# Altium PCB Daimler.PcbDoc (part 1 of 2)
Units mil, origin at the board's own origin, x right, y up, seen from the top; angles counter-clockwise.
Board outline 11850 x 8035 mil, 2 copper layers (Top Layer, Bottom Layer); 112 components, 172 nets, 625 pads, 65 vias.
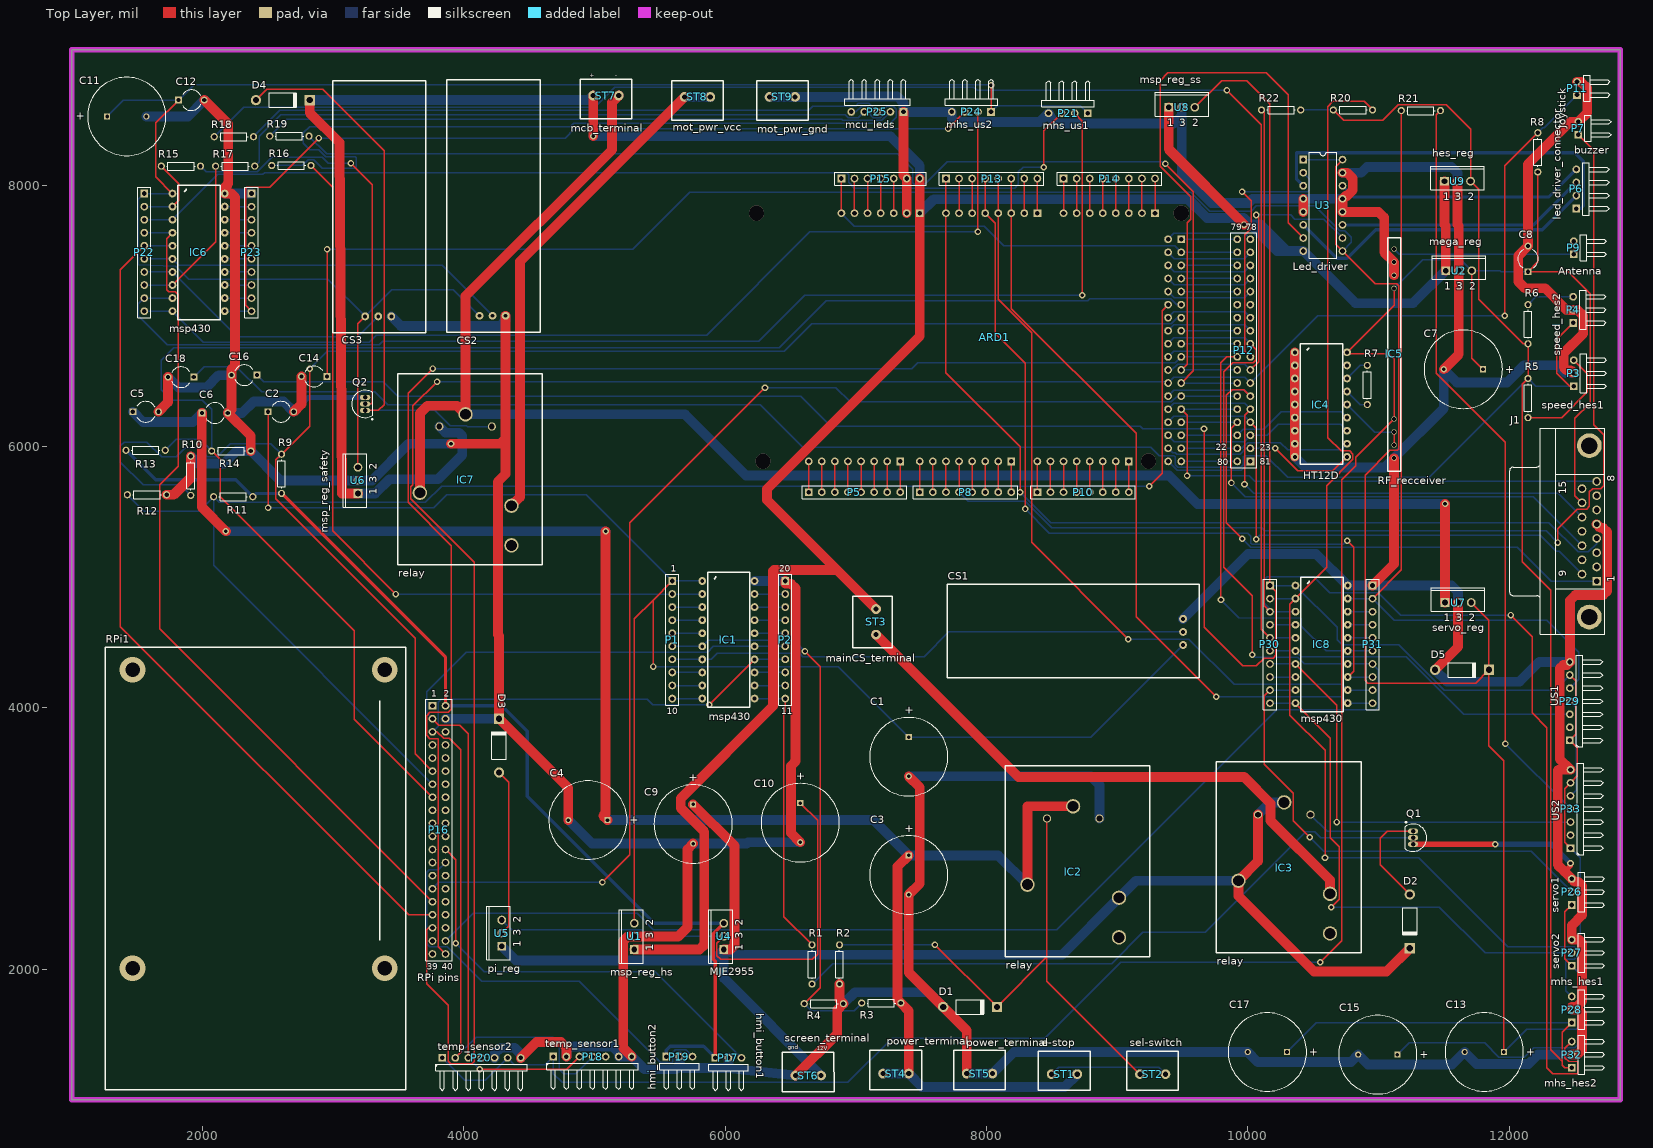
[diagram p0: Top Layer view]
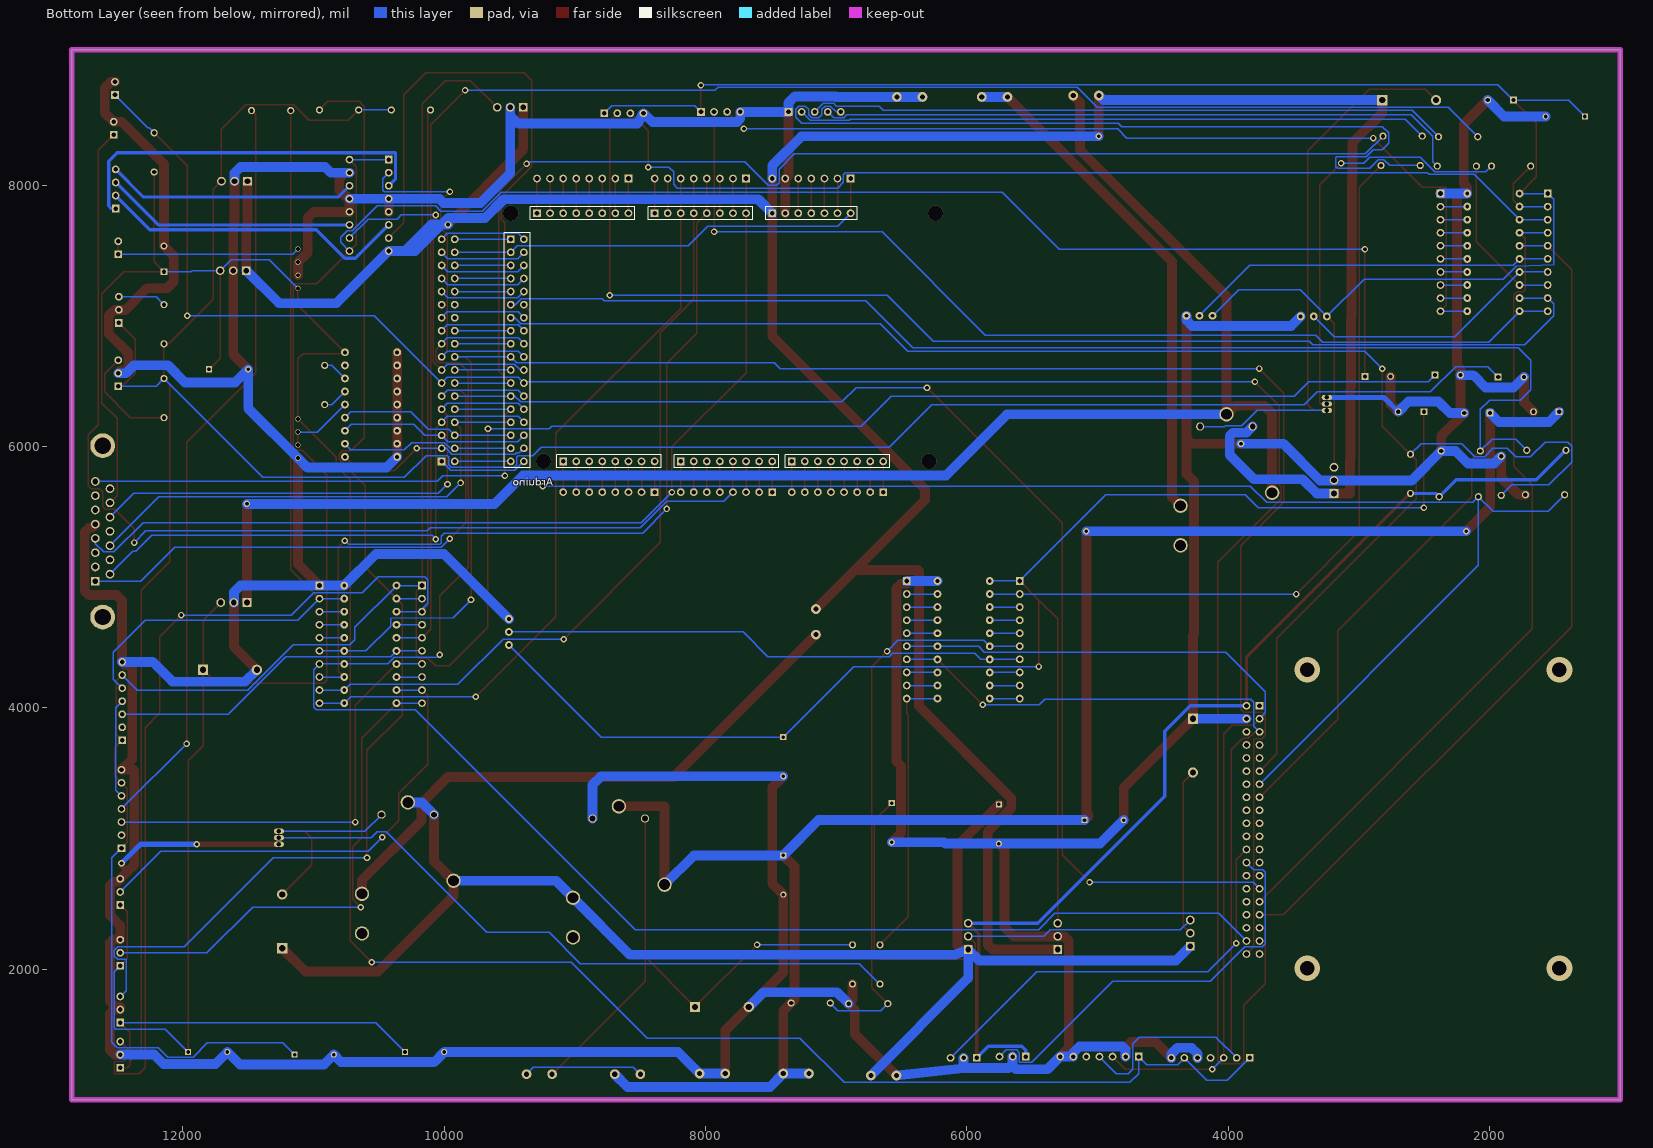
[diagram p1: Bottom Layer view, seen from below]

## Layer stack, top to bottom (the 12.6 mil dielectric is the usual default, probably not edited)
Top Solder: solder mask 0.4, Solder Resist, Dk 3.5
Top Layer: signal copper 1.4
Dielectric 1: dielectric 12.6, FR-4, Dk 4.8
Bottom Layer: signal copper 1.4
Bottom Solder: solder mask 0.4, Solder Resist, Dk 3.5

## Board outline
1000,1000 1000,9035 12850,9035 12850,1000

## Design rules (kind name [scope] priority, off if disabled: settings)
Clearance [All] p1: gap=10
PolygonConnect [All] p1: connectstyle=Relief reliefconductorwidth=10 reliefentries=4 polygonreliefangle="90 Angle" airgapwidth=10
RoutingVias [All] p1: holewidth=28 width=50 viastyle="Through Hole" minholewidth=28 minwidth=50 maxholewidth=28 maxwidth=50
SolderMaskExpansion [All] p1: expansion=4
Width "Schematic Width Constraint_11" [InNet('12V_MOTOR_DRIVER')] p1: maxlimit=80 minlimit=70 preferedwidth=75
Width "Schematic Width Constraint_10" [InNet('12V_MCB')] p2: maxlimit=80 minlimit=70 preferedwidth=75
Width "Schematic Width Constraint_9" [InNet('GND')] p3: maxlimit=80 minlimit=40 preferedwidth=75
Width "Schematic Width Constraint_8" [InNet('12V_TO_MAINCS')] p4: maxlimit=80 minlimit=70 preferedwidth=75
Width "Schematic Width Constraint_7" [InNet('12V_RPI')] p5: maxlimit=80 minlimit=70 preferedwidth=75
Width "Schematic Width Constraint_6" [InNet('12V_MAIN')] p6: maxlimit=80 minlimit=70 preferedwidth=75
Width "Schematic Width Constraint_3" [InNet('LED_SINK')] p7: maxlimit=30 minlimit=20 preferedwidth=25
Width "Schematic Width Constraint_2" [InNet('GREEN_OP')] p8: maxlimit=30 minlimit=20 preferedwidth=25
Width "Schematic Width Constraint_1" [InNet('BLUE_OP')] p9: maxlimit=30 minlimit=20 preferedwidth=25
Width "Schematic Width Constraint_5" [InNet('VCC_PI')] p10: maxlimit=30 minlimit=20 preferedwidth=25
Width "Schematic Width Constraint_4" [InNet('RED_OP')] p11: maxlimit=30 minlimit=20 preferedwidth=25
Width "Schematic Width Constraint" [InNet('12V')] p12: maxlimit=80 minlimit=70 preferedwidth=75
Width [All] p13: maxlimit=10 minlimit=10 preferedwidth=10
30 further rules are at their usual default settings.

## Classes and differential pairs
component class HardStop: C1 C2 C3 C4 C5 C6 CS1 D1 D2 IC1 IC2 IC3 P1 P2 Q1 R1 R2 R3 R4 ST1 ST2 ST3 ST4 ST5 U1
component class Navigation: ARD1 C7 C8 IC4 IC5 J1 P3 P4 P5 P6 P7 P8 P9 P10 P11 P12 P13 P14 P15 R5 R6 R7 R8 U2 U3
component class RPi: C9 C10 D3 P16 P17 P18 P19 P20 R9 R10 R11 R12 R13 R14 RPi1 ST6 U4 U5
component class Safety: C11 C12 CS2 CS3 D4 IC6 IC7 P21 P22 P23 P24 P25 Q2 R15 R16 R17 R18 R19 ST7 ST8 ST9 U6
component class SoftStop: C13 C14 C15 C16 C17 C18 D5 IC8 P26 P27 P28 P29 P30 P31 P32 P33 R20 R21 R22 U7 U8 U9

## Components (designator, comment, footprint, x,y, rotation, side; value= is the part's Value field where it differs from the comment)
ARD1 "Arduino" Arduino 7790,6785 r0 top
C1 "Cap Pol1" RB7.6-15 7405,3625 r90 top
C2 "Cap2" CAPR5-4X5 2600,6265 r0 top
C3 "Cap Pol1" RB7.6-15 7405,2720 r90 top
C4 "Cap Pol1" RB7.6-15 4950,3140 r0 top
C5 "Cap2" CAPR5-4X5 1565,6265 r0 top
C6 "Cap2" CAPR5-4X5 2095,6255 r0 top
C7 "Cap" RB7.6-15 11650,6590 r0 top
C8 "Cap2" CAPR5-4X5 12145,7435 r90 top
C9 "Cap" RB7.6-15 5755,3110 r90 top
C10 "Cap" RB7.6-15 6575,3120 r90 top
C11 "Cap" RB7.6-15 1420,8525 r180 top
C12 "Cap2" CAPR5-4X5 1915,8650 r0 top
C13 "Cap" RB7.6-15 11810,1365 r0 top
C14 "Cap2" CAPR5-4X5 2855,6535 r180 top
C15 "Cap" RB7.6-15 10995,1345 r0 top
C16 "Cap2" CAPR5-4X5 2320,6545 r180 top
C17 "Cap Pol1" RB7.6-15 10150,1365 r0 top
C18 "Cap2" CAPR5-4X5 1835,6530 r180 top
CS1 "CS3" ACS712 9405,4565 r180 top
CS2 "CS1" ACS712 4205,7100 r90 top
CS3 "CS2" ACS712 3330,7095 r90 top
D1 "flyback relay" DO-41 7875,1710 r0 top
D2 "flyback relay" DO-41 11240,2365 r270 top
D3 "cur_amp" DO-41 4270,3710 r90 top
D4 "flyback relay" DO-41 2615,8650 r0 top
D5 "Diode 1N4001" DO-41 11640,4290 r0 top
IC1 "msp430" msp430 6035,4575 r270 top
IC2 "relay" "relay JQX 15F" 8665,2825 r90 top
IC3 "relay" "relay JQX 15F" 10280,2855 r90 top
IC4 "HT12D" HT12D 10575,6325 r270 top
IC5 "RF_recceiver" RF_434_receiver 11120,6705 r90 top
IC6 "msp430" msp430 1980,7540 r270 top
IC7 "relay" "relay JQX 15F" 4015,5825 r90 top
IC8 "msp430" msp430 10575,4540 r270 top
J1 "D Connector 15" DSUB1.385-2H15 12240,5350 r90 top
P1 "hs_connector1" HDR1X10 5595,4970 r270 top
P2 "hs_connector2" HDR1X10 6460,4970 r270 top
P3 "speed_hes1" HDR1X3H 12495,6460 r90 top
P4 "speed_hes2" HDR1X3H 12490,6945 r90 top
P5 "Header 8" HDR1X8 6640,5650 r0 top
P6 "led_driver_connector" HDR1X4H 12515,7820 r90 top
P7 "buzzer" HDR1X2H 12530,8385 r90 top
P8 "Header 8" HDR1X8 7490,5650 r0 top
P9 "Antenna" HDR1X2H 12495,7470 r90 top
P10 "Header 8" HDR1X8 8390,5650 r0 top
P11 "Joystick" HDR1X2H 12520,8690 r90 top
P12 "Header 18X2" HDR2X18 10020,5885 r90 top
P13 "Header 8" HDR1X8 7690,8050 r0 top
P14 "Header 8" HDR1X8 8590,8050 r0 top
P15 "Header 7" HDR1X7 6890,8050 r0 top
P16 "RPi pins" HDR2X20 3760,4015 r270 top
P17 "hmi_button1" HDR1X3H 5925,1320 r0 top
P18 "temp_sensor1" HDR1X7H 4685,1330 r0 top
P19 "hmi_button2" HDR1X3H 5550,1330 r0 top
P20 "temp_sensor2" HDR1X7H 3835,1320 r0 top
P21 "mhs_us1" HDR1X4H 8775,8550 r180 top
P22 "safety_connector1" HDR1X10 1555,7935 r270 top
P23 "safety_connector2" HDR1X10 2375,7935 r270 top
P24 "mhs_us2" HDR1X4H 8035,8560 r180 top
P25 "mcu_leds" HDR1X5H 7365,8560 r180 top
P26 "servo1" HDR1X3H 12480,2490 r90 top
P27 "servo2" HDR1X3H 12480,2025 r90 top
P28 "mhs_hes1" HDR1X3H 12480,1590 r90 top
P29 "US1" HDR1X7H 12465,3750 r90 top
P30 "ss_connector1" HDR1X10 10170,4935 r270 top
P31 "ss_connector2" HDR1X10 10955,4935 r270 top
P32 "mhs_hes2" HDR1X3H 12480,1245 r90 top
P33 "US2" HDR1X7H 12470,2925 r90 top
Q1 "NPN" TO-226-AA 11265,3005 r180 top
Q2 "NPN" TO-226-AA 3245,6325 r0 top
R1 "Res1" AXIAL-0.3 6665,2035 r90 top
R2 "Res1" AXIAL-0.3 6875,2035 r90 top
R3 "Res1" AXIAL-0.3 7195,1740 r180 top
R4 "Res1" AXIAL-0.3 6755,1735 r0 top
R5 "Res1" AXIAL-0.3 12145,6370 r90 top
R6 "Res1" AXIAL-0.3 12145,6935 r270 top
R7 "Res1" AXIAL-0.3 10915,6470 r270 top
R8 "Res1" AXIAL-0.3 12220,8250 r90 top
R9 "Res1" AXIAL-0.3 2605,5790 r90 top
R10 "Res1" AXIAL-0.3 1910,5775 r90 top
R11 "Res1" AXIAL-0.3 2235,5615 r180 top
R12 "Res1" AXIAL-0.3 1575,5630 r180 top
R13 "Res1" AXIAL-0.3 1565,5970 r0 top
R14 "Res1" AXIAL-0.3 2220,5965 r180 top
R15 "Res1" AXIAL-0.3 1835,8145 r180 top
R16 "Res1" AXIAL-0.3 2680,8150 r180 top
R17 "Res1" AXIAL-0.3 2250,8145 r0 top
R18 "Res1" AXIAL-0.3 2240,8370 r0 top
R19 "Res1" AXIAL-0.3 2665,8375 r180 top
R20 "Res1" AXIAL-0.3 10805,8575 r0 top
R21 "Res1" AXIAL-0.3 11325,8570 r180 top
R22 "Res1" AXIAL-0.3 10255,8575 r180 top
RPi1 "raspberrypi" raspberrypi 1465,4290 r270 top
ST1 "e-stop" screw_terminal_5 8610,1195 r180 top
ST2 "sel-switch" screw_terminal_5 9285,1195 r180 top
ST3 "mainCS_terminal" screw_terminal_5 7155,4670 r270 top
ST4 "power_terminal" screw_terminal_5 7320,1200 r180 top
ST5 "power_terminal" screw_terminal_5 7960,1200 r180 top
ST6 "screen_terminal" screw_terminal_5 6650,1185 r180 top
ST7 "mcb_terminal" screw_terminal_5 5075,8685 r0 top
ST8 "mot_pwr_vcc" screw_terminal_5 5775,8675 r0 top
ST9 "mot_pwr_gnd" screw_terminal_5 6425,8675 r0 top
U1 "msp_reg_hs" TO220ABN 5305,2250 r90 top
U2 "mega_reg" TO220ABN 11615,7345 r0 top
U3 "Led_driver" DIP16 10575,7845 r270 top
U4 "MJE2955" TO220ABN 5990,2250 r90 top
U5 "pi_reg" TO220ABN 4290,2275 r90 top
U6 "msp_reg_safety" TO220ABN 3190,5740 r90 top
U7 "servo_reg" TO220ABN 11610,4805 r0 top
U8 "msp_reg_ss" TO220ABN 9495,8595 r0 top
U9 "hes_reg" TO220ABN 11605,8030 r0 top

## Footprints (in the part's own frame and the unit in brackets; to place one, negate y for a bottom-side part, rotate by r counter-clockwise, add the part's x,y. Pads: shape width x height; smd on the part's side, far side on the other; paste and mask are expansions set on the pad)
ACS712 [mil]
  round 60 hole 30: 1(-100,85) 2(-100,-15) 3(-100,-115)
  silkscreen extent -225,-380 1705,335, body extent -230,-380 1705,335, height 787
Arduino [mm] "Arduino Mega 2560"
  rect 1.5x1.5 hole 0.9: 0(10.16,-22.86) 8(-11.43,-22.86) 21(33.02,-22.86) 59(-7.62,25.4) 67(15.24,25.4) 75(38.1,25.4) 79(43.18,20.32)
  round 1.5 hole 0.9: 1(7.62,-22.86) 2(5.08,-22.86) 3(2.54,-22.86) 4(0,-22.86) 5(-2.54,-22.86) 6(-5.08,-22.86) 7(-7.62,-22.86) 9(-13.97,-22.86) 10(-16.51,-22.86) 11(-19.05,-22.86) 12(-21.59,-22.86) 13(-24.13,-22.86) 14(15.24,-22.86) 15(17.78,-22.86) 16(20.32,-22.86) 17(22.86,-22.86) 18(25.4,-22.86) 19(27.94,-22.86) 20(30.48,-22.86) 22(40.64,-20.32) 23(43.18,-20.32) 24(40.64,-17.78) 25(43.18,-17.78) 26(40.64,-15.24) 27(43.18,-15.24) 28(40.64,-12.7) 29(43.18,-12.7) 30(40.64,-10.16) 31(43.18,-10.16) 32(40.64,-7.62) 33(43.18,-7.62) 34(40.64,-5.08) 35(43.18,-5.08) 36(40.64,-2.54) 37(43.18,-2.54) 38(40.64,0) 39(43.18,0) 40(40.64,2.54) 41(43.18,2.54) 42(40.64,5.08) 43(43.18,5.08) 44(40.64,7.62) 45(43.18,7.62) 46(40.64,10.16) 47(43.18,10.16) 48(40.64,12.7) 49(43.18,12.7) 50(40.64,15.24) 51(43.18,15.24) 52(40.64,17.78) 53(-22.86,25.4) 53(43.18,17.78) 54(-20.32,25.4) 55(-17.78,25.4) 56(-15.24,25.4) 57(-12.7,25.4) 58(-10.16,25.4) 60(-2.54,25.4) 61(0,25.4) 62(2.54,25.4) 63(5.08,25.4) 64(7.62,25.4) 65(10.16,25.4) 66(12.7,25.4) 68(20.32,25.4) 69(22.86,25.4) 70(25.4,25.4) 71(27.94,25.4) 72(30.48,25.4) 73(33.02,25.4) 74(35.56,25.4) 76(-26.67,-22.86) 77(-29.21,-22.86) 78(40.64,20.32) 80(43.18,-22.86) 81(40.64,-22.86)
AXIAL-0.3 [mm] "Axial Device, Thru-Hole; 2 Leads; 0.3 in Pin Spacing"
  round 1.4 hole 0.85: 1(-3.81,0) 2(3.81,0)
  silkscreen extent -2.77,-0.76 2.77,0.76
CAPR5-4X5 [mm] "Capacitor; 2 Leads"
  rect 1.35x1.35 hole 0.8: 1(-2.5,0)
  round 1.35 hole 0.8: 2(2.5,0)
  silkscreen extent -1.69,-2 1.82,2
DIP16 [mm] "DIP; 16 Leads; Row Spacing 7.62 mm; Pitch 2.54 mm"
  rect 1.5x1.5 hole 0.9: 1(-8.89,-3.81)
  round 1.5 hole 0.9: 2(-6.35,-3.81) 3(-3.81,-3.81) 4(-1.27,-3.81) 5(1.27,-3.81) 6(3.81,-3.81) 7(6.35,-3.81) 8(8.89,-3.81) 9(8.89,3.81) 10(6.35,3.81) 11(3.81,3.81) 12(1.27,3.81) 13(-1.27,3.81) 14(-3.81,3.81) 15(-6.35,3.81) 16(-8.89,3.81)
  silkscreen extent -10.3,-2.65 10.3,2.65
DO-41 [mm] "Diode, Axial; Body 5.2 x 2.7 mm (LxDia. max), Lead Dia. 0.86 mm (max)"
  round 2 hole 1.2: 1(-5.23,0)
  rect 2x2 hole 1.2: 2(5.23,0)
  silkscreen extent -2.65,-1.4 2.75,1.4
DSUB1.385-2H15 [mm] "Connector; D Subminiature; 15 Position; Right Angle; Pitch 1.385 mm"
  rect 1.69x1.69 hole 1.09: 1(-9.695,-10.92)
  round 1.69 hole 1.09: 2(-6.925,-10.92) 3(-4.155,-10.92) 4(-1.385,-10.92) 5(1.385,-10.92) 6(4.155,-10.92) 7(6.925,-10.92) 8(9.695,-10.92) 9(-8.31,-8.08) 10(-5.54,-8.08) 11(-2.77,-8.08) 12(0,-8.08) 13(2.77,-8.08) 14(5.54,-8.08) 15(8.31,-8.08)
  round 4.8 hole 3.18: 16(-16.66,-9.5) 17(16.66,-9.5)
  silkscreen extent -20,-12.5 20,6
HDR1X2H [mm] "Connector; Header; 2 Position; Right Angle"
  rect 1.5x1.5 hole 0.9: 1(0,0)
  round 1.5 hole 0.9: 2(2.54,0)
  silkscreen extent -1.27,-6.35 3.81,-1.27
HDR1X3H [mm] "Connector; Header; 3 Position; Right Angle"
  rect 1.5x1.5 hole 0.9: 1(0,0)
  round 1.5 hole 0.9: 2(2.54,0) 3(5.08,0)
  silkscreen extent -1.27,-6.35 6.35,-1.27
HDR1X4H [mm] "Connector; Header; 4 Position; Right Angle"
  rect 1.5x1.5 hole 0.9: 1(0,0)
  round 1.5 hole 0.9: 2(2.54,0) 3(5.08,0) 4(7.62,0)
  silkscreen extent -1.27,-6.35 8.89,-1.27
HDR1X5H [mm] "Connector; Header; 5 Position; Right Angle"
  rect 1.5x1.5 hole 0.9: 1(0,0)
  round 1.5 hole 0.9: 2(2.54,0) 3(5.08,0) 4(7.62,0) 5(10.16,0)
  silkscreen extent -1.27,-6.35 11.43,-1.27
HDR1X7 [mm] "Connector; Header; 7 Position"
  rect 1.5x1.5 hole 0.9: 1(0,0)
  round 1.5 hole 0.9: 2(2.54,0) 3(5.08,0) 4(7.62,0) 5(10.16,0) 6(12.7,0) 7(15.24,0)
  silkscreen extent -1.27,-1.27 16.51,1.27
HDR1X7H [mm] "Connector; Header; 7 Position; Right Angle"
  rect 1.5x1.5 hole 0.9: 1(0,0)
  round 1.5 hole 0.9: 2(2.54,0) 3(5.08,0) 4(7.62,0) 5(10.16,0) 6(12.7,0) 7(15.24,0)
  silkscreen extent -1.27,-6.35 16.51,-1.27
HDR1X8 [mm] "Connector; Header; 8 Position"
  rect 1.5x1.5 hole 0.9: 1(0,0)
  round 1.5 hole 0.9: 2(2.54,0) 3(5.08,0) 4(7.62,0) 5(10.16,0) 6(12.7,0) 7(15.24,0) 8(17.78,0)
  silkscreen extent -1.27,-1.27 19.05,1.27
HDR1X10 [mm] "Connector; Header; 10 Position"
  rect 1.5x1.5 hole 0.9: 1(0,0)
  round 1.5 hole 0.9: 2(2.54,0) 3(5.08,0) 4(7.62,0) 5(10.16,0) 6(12.7,0) 7(15.24,0) 8(17.78,0) 9(20.32,0) 10(22.86,0)
  silkscreen extent -1.27,-1.27 24.13,1.27
HDR2X18 [mm] "Connector; Header; 18x2 Position"
  rect 1.5x1.5 hole 0.9: 1(0,0)
  round 1.5 hole 0.9: 2(0,2.54) 3(2.54,0) 4(2.54,2.54) 5(5.08,0) 6(5.08,2.54) 7(7.62,0) 8(7.62,2.54) 9(10.16,0) 10(10.16,2.54) 11(12.7,0) 12(12.7,2.54) 13(15.24,0) 14(15.24,2.54) 15(17.78,0) 16(17.78,2.54) 17(20.32,0) 18(20.32,2.54) 19(22.86,0) 20(22.86,2.54) 21(25.4,0) 22(25.4,2.54) 23(27.94,0) 24(27.94,2.54) 25(30.48,0) 26(30.48,2.54) 27(33.02,0) 28(33.02,2.54) 29(35.56,0) 30(35.56,2.54) 31(38.1,0) 32(38.1,2.54) 33(40.64,0) 34(40.64,2.54) 35(43.18,0) 36(43.18,2.54)
  silkscreen extent -1.27,-1.27 44.45,3.81
HDR2X20 [mm] "Connector; Header; 20x2 Position"
  rect 1.5x1.5 hole 0.9: 1(0,0)
  round 1.5 hole 0.9: 2(0,2.54) 3(2.54,0) 4(2.54,2.54) 5(5.08,0) 6(5.08,2.54) 7(7.62,0) 8(7.62,2.54) 9(10.16,0) 10(10.16,2.54) 11(12.7,0) 12(12.7,2.54) 13(15.24,0) 14(15.24,2.54) 15(17.78,0) 16(17.78,2.54) 17(20.32,0) 18(20.32,2.54) 19(22.86,0) 20(22.86,2.54) 21(25.4,0) 22(25.4,2.54) 23(27.94,0) 24(27.94,2.54) 25(30.48,0) 26(30.48,2.54) 27(33.02,0) 28(33.02,2.54) 29(35.56,0) 30(35.56,2.54) 31(38.1,0) 32(38.1,2.54) 33(40.64,0) 34(40.64,2.54) 35(43.18,0) 36(43.18,2.54) 37(45.72,0) 38(45.72,2.54) 39(48.26,0) 40(48.26,2.54)
  silkscreen extent -1.27,-1.27 49.53,3.81
HT12D [mil]
  round 60 hole 30: 1(-395,-215) 2(-295,-215) 3(-195,-215) 4(-95,-215) 5(5,-215) 6(105,-215) 7(205,-215) 8(305,-215) 9(405,-215) 10(405,185) 11(305,185) 12(205,185) 13(105,185) 14(5,185) 15(-95,185) 16(-195,185) 17(-295,185) 18(-395,185)
  silkscreen extent -460,-175 460,150, body extent -460,-175 455,150, height 325
msp430 [mil]
  round 60 hole 30: 1(-395,-210) 2(-295,-210) 3(-195,-210) 4(-95,-210) 5(5,-210) 6(105,-210) 7(205,-210) 8(305,-210) 9(405,-210) 10(505,-210) 11(505,190) 12(405,190) 13(305,190) 14(205,190) 15(105,190) 16(5,190) 17(-95,190) 18(-195,190) 19(-295,190) 20(-395,190)
  silkscreen extent -460,-170 570,155, body extent -460,-170 565,155, height 325
raspberrypi [mil]
  silkscreen extent -173,-209 3213,2091, body extent 2766,53 3301,1781, height 591
RB7.6-15 [mm] "Polarized Capacitor (Radial); 2 Leads"
  rect 1.2x1.2 hole 0.7: 1(3.81,0)
  round 1.2 hole 0.7: 2(-3.81,0)
  silkscreen extent -7.62,-7.62 7.62,7.62
"relay JQX 15F" [mm]
  round 2.8 hole 2.1: 1(-14.8,-8.875) 2(-7.1,-8.875) 3(-4.55,8.925) 6(10.675,0.05)
  round 1.6 hole 1.1: 4(8.3,5.125) 5(8.3,-5.075)
  silkscreen extent -18.52,-14.9 18.55,13.23, body extent -18.52,-14.88 18.5,13.15, height 20.4
RF_434_receiver [mil]
  round 40 hole 30: 1(-795,0) 2(-695,0) 3(-595,0) 4(-495,0) 5(505,0) 6(605,0) 7(705,0) 8(805,0)
  silkscreen extent -895,-50 890,50, body extent -895,-45 890,50, height 413
screw_terminal_5 [mm]
  round 1.9 hole 1: 1(-2.159,0) 2(2.819,0)
  silkscreen extent -4.67,-4.5 5.38,3.12, body extent -4.52,-4.34 5.23,3, height 10
TO220ABN [mm] "TO, Thru-Hole, Vertical, Heatsink Mounted; 3 In-Line Leads; Pitch 2.54 mm; Pin sequence 1, 3, 2"
  rect 1.7x1.7 hole 1.1: 1(-2.54,0)
  round 1.7 hole 1.1: 2(2.54,0) 3(0,0)
  silkscreen extent -5.2,-1.7 5.2,2.9
TO-226-AA [mm] "TO, Flat Index; 3 In-Line, Axial Leads; Body Dia. 4.8mm; Leads 0.55 x 0.51 mm (max)"
  oval 2x1 hole 0.9: 1(0,-1.27) 2(0,0) 3(0,1.27)
  silkscreen extent -2.65,-3.13 1.52,2.65, body extent -2.66,-2.66 1.52,2.66, height 5.33

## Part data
C1 C3 C4 C17: "Polarized Capacitor (Radial)"
C2 C5 C6 C8 C12 C14 C16 C18: "Capacitor"
C7 C9 C10 C11 C13 C15: library part "Cap Pol1", "Polarized Capacitor (Radial)"
CS1 CS2 CS3: library part ACS712
D1 D2 D3 D4: library part "Diode 1N4001", "1 Amp General Purpose Rectifier"
D5: "1 Amp General Purpose Rectifier"
IC2 IC3 IC7: library part "relay JQX-15F"
IC5: library part RF434_receiver
J1: "Receptacle Assembly, 15 Position, Right Angle"
P1 P2 P22 P23 P30 P31: library part "Header 10", "Header, 10-Pin"
P3 P4 P17 P19 P26 P27 P28 P32: library part "Header 3H", "Header, 3-Pin, Right Angle"
P5 P8 P10 P13 P14: "Header, 8-Pin"
P6 P21 P24: library part "Header 4H", "Header, 4-Pin, Right Angle"
P7 P9 P11: library part "Header 2H", "Header, 2-Pin, Right Angle"
P12: "Header, 18-Pin, Dual row"
P15: "Header, 7-Pin"
P16: library part "Header 20X2", "Header, 20-Pin, Dual row"
P18 P20 P29 P33: library part "Header 7H", "Header, 7-Pin, Right Angle"
P25: library part "Header 5H", "Header, 5-Pin, Right Angle"
Q1 Q2: "NPN Bipolar Transistor"
R1 R2 R3 R4 R5 R6 R7 R8 R9 R10 R11 R12 R13 R14 R15 R16 R17 R18 R19 R20 R21 R22: "Resistor"
ST1 ST2 ST3 ST4 ST5 ST6 ST7 ST8 ST9: library part screw_terminal
U1 U2 U4 U5 U6 U7 U8 U9: library part L7805CV, "Positive Voltage Regulator"
U3: library part L293D, "Push-Pull Four Channel Driver With Diode"

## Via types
v1: diameter 50, hole 28, Top Layer to Bottom Layer, 57 vias
v2: diameter 196.85, hole 110.24, Top Layer to Bottom Layer, 4 vias
v3: diameter 118.11, hole 118.11, Top Layer to Bottom Layer, 4 vias

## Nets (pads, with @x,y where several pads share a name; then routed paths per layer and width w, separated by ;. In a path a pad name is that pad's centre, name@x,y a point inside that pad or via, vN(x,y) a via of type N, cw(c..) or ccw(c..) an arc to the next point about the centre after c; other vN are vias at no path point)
12V: ARD1.59 D4.2 IC7.4 P15.7 ST3.1 ST7.1 U1.1 U2.1 U3.8 U6.1 U8.1 U9.1 | length 24818.3
  Top Layer w75: D4.2@2820.91,8650 2820.91,8553.09 3047.5,8326.5 3068,5640 U6.1@3190,5640 ; v1(4990,8373) ST7.1@4990,8685 ; U1.1@5305,2150 5804,2150 5840,2186 5840,3051 5660,3231 5660,3305 6367,4012 6367,5047 6375,5055 6855,5055 ; ST3.1@7155,4755 6855,5055 ; P15.7@7490,8050 ARD1.59@7490,7785 7490,6845 6320,5675 6320,5590 6855,5055 ; U8.1@9395,8595 9395,8274 v1(9971,7698) ; U9.1@11505,8030 11505,7698 11515,7688 U2.1@11515,7345
  Bottom Layer w75: D4.2@2820.91,8650 4955,8650 ST7.1@4990,8685 ; U6.1@3190,5640 3321.51,5640 3430,5748.49 3803.49,5748.49 3988,5933 3988,6080 3963,6105 3860,6105 IC7.4@3813.23,6151.77 ; v1(4990,8373) 7265,8373 7490,8148 P15.7@7490,8050 ; ARD1.59@7490,7785 7596.56,7891.56 9544.44,7891.56 9687.73,7748.27 9969.73,7748.27 10020,7698 ; v1(9971,7698) 10020,7698 ; U2.1@11515,7345 11266,7096 10824,7096 U3.8@10425,7495 10300,7495 ; 10020,7698 10097,7698 10300,7495 ; 10020,7698 10223,7495 10300,7495
12V_MAIN: C3.1 C4.1 C5.1 C6.1 IC2.3 IC2.6 R3.1 ST1.1 ST4.1 ST4.2 | length 14386.9
  Top Layer w75: C6.1@1996.57,6255 1996.57,6198.85 1994,6196.28 1994,5948 1995,5947 1995,5534 v1(2179,5350) ; v1(5085,5350) 5085,3191 5067,3173 C4.1@5100,3140 ; ST4.1@7405,1200 7405,1680 R3.1@7345,1740 7320,1765 7320,2785 C3.1@7405,2870 ; IC2.3@8313.62,2645.87 8313.62,3245 8313.9,3245.28 IC2.6@8663.03,3245.28
  Bottom Layer w75: C5.1@1466.57,6265 1545.57,6186 1927.57,6186 C6.1@1996.57,6255 ; v1(2179,5350) v1(5085,5350) ; C4.1@5100,3140 7135,3140 C3.1@7405,2870 8089.49,2870 IC2.3@8313.62,2645.87 ; ST4.2@7209,1200 ST4.1@7405,1200 7507,1098 8598,1098 ST1.1@8695,1195
12V_MCB: IC7.3 IC7.6 ST7.2 U7.1 | length 12469.2
  Top Layer w75: IC7.3@3663.62,5645.87 3663.62,6253.93 3720,6310.31 3948,6310.31 IC7.6@4013.03,6245.28 4013.03,7150.03 5133,8270 5133,8632 ST7.2@5186,8685 ; U7.1@11510,4805 v1(11510,5560)
  Bottom Layer w75: IC7.6@4013.03,6245.28 5691.72,6245.28 6159,5778 9397,5778 9615,5560 v1(11510,5560)
12V_MOTOR_DRIVER: IC7.2 ST8.1 ST8.2 | length 3874.6
  Top Layer w75: IC7.2@4364.41,5545.47 4430,5611.06 4430,7415 ST8.1@5690,8675
  Bottom Layer w75: ST8.1@5690,8675 ST8.2@5886,8675
12V_RPI: C9.1 D2.2 IC2.2 IC3.3 IC3.4 IC3.6 ST6.1 U4.1 U5.1 | length 11089.1
  Top Layer w75: C9.1@5755,3260 6071,2944 6071,2180 6041,2150 U4.1@5990,2150 ; IC3.4@10078.23,3181.77 10078.23,2825.47 IC3.3@9928.62,2675.87 9928.62,2558.38 10507,1980 11060.91,1980 D2.2@11240,2159.09
  Bottom Layer w75: U5.1@4290,2175 4400,2065 5905,2065 U4.1@5990,2150 ; ST6.1@6735,1185 5990,1930 U4.1@5990,2150 ; IC3.3@9928.62,2675.87 9144.8,2675.87 IC2.2@9014.41,2545.47 8577.94,2109 6091,2109 U4.1@5990,2150 ; IC3.4@10078.23,3181.77 10171.73,3275.28 IC3.6@10278.03,3275.28
12V_TO_MAINCS: IC3.2 ST3.2 | length 4434.9
  Top Layer w75: ST3.2@7155,4559 8245,3469 9973,3469 10175,3267 10175,3135 10629.41,2680.59 IC3.2@10629.41,2575.47
BATTERY_LVL: IC1.6 P1.6 R3.2 R4.1 | length 4351
  Top Layer w10: R4.1@6605,1735 6728,1858 6728,4315 v1(6611,4432)
  Bottom Layer w10: P1.6@5595,4470 IC1.6@5825,4470 5870,4515 6528,4515 v1(6611,4432) ; R4.1@6605,1735 6657.5,1682.5 6987.5,1682.5 R3.2@7045,1740
BLUE: ARD1.35 P12.16 U3.7 | length 4990.3
  Top Layer w10: ARD1.35@9490,6585 9535,6630 9535,7711 9564.06,7740.06 9564.06,7908.94 9330,8143 9330,8800 9389,8859 10142,8859 10309,8692 10309,7711 U3.7@10425,7595
  Bottom Layer w10: ARD1.35@9490,6585 P12.16@9920,6585
BLUE_OP: P6.2 U3.6 | length 2394.4
  Bottom Layer w25: U3.6@10425,7695 10680,7440 10760,7440 10978,7658 12253,7658 P6.2@12515,7920
BUZZER_OP: ARD1.4 P7.1 P8.4 | length 8402.5
  Top Layer w10: P8.4@7790,5650 ARD1.4@7790,5885 ; v1(12372,5264) 12372,5371 12520,5519 12593,5519 12614,5540 12614,5651 12640,5677 12701,5677 12724,5700 12724,6088 12648,6164 12648,8267 P7.1@12530,8385
  Bottom Layer w10: P8.4@7790,5650 7859,5581 8296,5581 8501,5376 10106,5376 10129,5353 12283,5353 v1(12372,5264)
CS_IN1: CS2.2 IC6.6 P22.6 | length 2845.2
  Bottom Layer w10: P22.6@1555,7435 IC6.6@1770,7435 1820,7385 3835,7385 CS2.2@4220,7000
CS_IN2: CS3.2 IC6.7 P22.7 | length 2059.2
  Bottom Layer w10: P22.7@1555,7335 IC6.7@1770,7335 2265,6840 3190,6840 CS3.2@3345,6995
CS_IN3: CS1.2 IC1.7 P1.7 | length 4016.8
  Bottom Layer w10: P1.7@5595,4370 IC1.7@5825,4370 5893,4370 5938,4415 6570.5,4415 6594.42,4391.08 7522.08,4391.08 7711,4580 CS1.2@9505,4580
D0: ARD1.22 IC4.10 P12.3 | length 1523.7
  Top Layer w10: v1(10210,5985) 10383,5812 10652,5812 IC4.10@10760,5920
  Bottom Layer w10: ARD1.22@9390,5985 9425.47,5949.53 9445,5949.53 9454.53,5940 9940.47,5940 9985.47,5985 P12.3@10020,5985 v1(10210,5985)
D1: ARD1.23 IC4.11 P12.4 | length 1330.5
  Bottom Layer w10: ARD1.23@9490,5985 P12.4@9920,5985 9955.47,5985 10000,6029.53 10250,6029.53 10305.53,5974 10714,5974 IC4.11@10760,6020
D2: ARD1.24 IC4.12 P12.5 | length 1464.9
  Bottom Layer w10: ARD1.24@9390,6085 9438,6037 9972,6037 P12.5@10020,6085 10148,6085 10232,6169 10711,6169 IC4.12@10760,6120
D3: ARD1.25 IC4.13 P12.6 | length 1363.2
  Bottom Layer w10: ARD1.25@9490,6085 P12.6@9920,6085 9965,6130 10121,6130 10256,6265 10715,6265 IC4.13@10760,6220
FORK_LEFT: ARD1.30 J1.1 P12.11 | length 4886
  Top Layer w10: v1(9957,5294) 9835,5416 9835,6390 9880,6435 9970,6435 P12.11@10020,6385
  Bottom Layer w10: ARD1.30@9390,6385 9435,6430 9975,6430 P12.11@10020,6385 ; v1(9957,5294) 10021,5230 12062,5230 12323.69,4968.31 J1.1@12669.92,4968.31
FORK_RIGHT: ARD1.29 J1.8 P12.10 | length 4110.9
  Top Layer w10: ARD1.29@9490,6285 9535,6240 v1(9535,5776)
  Bottom Layer w10: ARD1.29@9490,6285 P12.10@9920,6285 ; v1(9535,5776) 10011,5776 10055,5732 12607,5732 12607.31,5731.69 J1.8@12669.92,5731.69
FROM_MSP: IC6.5 P16.33 P22.5 | length 6507.1
  Top Layer w10: P22.5@1555,7535 1372,7352 1372,4620 3577,2415 P16.33@3760,2415
  Bottom Layer w10: P22.5@1555,7535 IC6.5@1770,7535
GND: ARD1.58 C1.2 C2.2 C3.2 C4.2 C5.2 C6.2 C7.2 C8.2 C9.2 C10.2 C11.2 C12.2 C13.2 C14.2 C15.2 C16.2 C17.2 C18.2 CS1.3 CS2.3 CS3.3 D1.1 D3.2 D5.1 IC1.20 IC2.5 IC4.1 IC4.2 IC4.3 IC4.4 IC4.5 IC4.6 IC4.7 IC4.8 IC4.9 IC5.1 IC5.6 IC5.7 IC6.20 IC8.20 J1.5 P2.1 P3.2 P4.2 P7.2 P11.2 P15.6 P16.4 P17.2 P18.2 P18.6 P18.7 P19.2 P20.5 P20.7 P21.4 P23.1 P24.4 P25.1 P26.3 P27.3 P28.2 P29.7 P31.1 P32.2 P33.7 Q1.3 Q2.3 R2.1 R4.2 R10.2 R12.1 R14.1 ST5.1 ST5.2 ST6.2 ST9.1 ST9.2 U1.3 U2.3 U3.4 U3.5 U3.12 U3.13 U3.15 U6.3 U7.3 U8.3 U9.3 | length 62466.5
  Top Layer w40: Q1.3@11265,2955 v1(11895,2955) ; 12425,2745 12470,2790 v1(12470,2810)
  Top Layer w75: C5.2@1663.43,6265 1736.57,6338.15 C18.2@1736.57,6530 ; R12.1@1725,5630 1780,5630 1910,5760 R10.2@1910,5925 ; C12.2@2013.43,8650 2197,8466.43 2197,8010 2170,7983 IC6.20@2170,7935 2220,7935 2248,7907 2248,6616.85 2221.57,6590.43 C16.2@2221.57,6545 2221.57,6283.15 C6.2@2193.43,6255 2370,6078.43 R14.1@2370,5965 ; C2.2@2698.43,6265 2756.57,6323.15 C14.2@2756.57,6535 ; v1(3902,6020) 4280,6020 4320,6060 ; CS2.3@4320,7000 4320,6060 ; P20.7@4435,1320 4556,1441 4744,1441 4785,1400 P18.2@4785,1330 ; C4.2@4800,3140 4800,3385.91 D3.2@4270,3915.91 4270,4550 4261,4559 4261,5730 4320,5789 4320,6060 ; P18.7@5285,1330 5220,1395 5220,2216 5254,2250 U1.3@5305,2250 5641,2250 5711,2320 5711,2916 C9.2@5755,2960 ; P2.1@6460,4970 6460,4948 6505,4948 6538,4915 6538,3590 6503,3555 6503,3042 C10.2@6575,2970 ; ST6.2@6539,1185 6858,1504 6858,1688 R4.2@6905,1735 6875,1765 R2.1@6875,1885 ; P25.1@7365,8560 7365,8075 P15.6@7390,8050 ARD1.58@7390,7785 ; C1.2@7405,3475 7490,3390 7490,2655 C3.2@7405,2570 7405,1974.09 D1.1@7669.09,1710 7849,1530.09 ST5.2@7849,1200 ; IC4.9@10360,5920 IC4.8@10360,6020 IC4.7@10360,6120 IC4.6@10360,6220 IC4.5@10360,6320 IC4.4@10360,6420 IC4.3@10360,6520 IC4.2@10360,6620 IC4.1@10360,6720 ; U3.5@10425,7795 U3.4@10425,7895 ; U3.15@10725,8095 10760,8095 10803,8052 10803,7960 10760,7917 10747,7917 U3.13@10725,7895 U3.12@10725,7795 11000,7795 11044,7751 11044,7486 IC5.7@11120,7410 IC5.6@11120,7310 ; P31.1@10955,4935 11120,5100 IC5.1@11120,5910 ; D5.1@11434.09,4290 11610,4465.91 U7.3@11610,4805 ; C7.2@11500,6590 11615,6705 U2.3@11615,7345 11615,7688 11605,7698 U9.3@11605,8030 ; P32.2@12480,1345 12523,1345 12558,1380 12558,1660 12528,1690 P28.2@12480,1690 12480,1710 12515,1710 12558,1753 12558,2200 12533,2225 P27.3@12480,2225 12480,2334 12558,2412 12558,2638 12528,2668 12502,2668 P26.3@12480,2690 12425,2745 12372,2798 12372,3520 12377,3525 P33.7@12470,3525 12387,3608 12387,4300 12415,4328 12443,4328 P29.7@12465,4350 12465,4820 12507,4862 12720,4862 12751,4893 12751,5346 12720,5377 12697.45,5377 J1.5@12669.92,5404.53 ; P3.2@12495,6560 12472,6583 12440,6583 12417.97,6605.03 12417.97,6714.97 12568,6865 12568,7000 12523,7045 P4.2@12490,7045 12440,7045 12274,7211 12120,7211 12070,7261 12070,7458.43 C8.2@12145,7533.43 12144,7581.43 12144,8160 12469,8485 P7.2@12530,8485 12598,8553 12598,8742 12550,8790 P11.2@12520,8790
  Bottom Layer w40: C2.2@2698.43,6265 2808.43,6375 Q2.3@3245,6375 ; v1(11895,2955) 12325,2955 v1(12470,2810)
  Bottom Layer w75: C11.2@1570,8525 1888.43,8525 C12.2@2013.43,8650 ; C18.2@1736.57,6530 1815.57,6451 2030,6451 2124,6545 C16.2@2221.57,6545 ; R10.2@1910,5925 1965.06,5869.94 2164.94,5869.94 2260,5965 R14.1@2370,5965 2595,5740 U6.3@3190,5740 3297.23,5740 3577.23,6020 v1(3902,6020) ; IC6.20@2170,7935 P23.1@2375,7935 ; C6.2@2193.43,6255 2303,6255 2392,6344 2619.43,6344 C2.2@2698.43,6265 ; CS3.3@3445,6995 3518,6922 4276,6922 4320,6966 CS2.3@4320,7000 ; P16.4@3860,3915 4065,3915 4065.91,3915.91 D3.2@4270,3915.91 ; P20.5@4235,1320 4235,1352.03 4280,1397.03 4389.88,1397.03 4435,1351.91 P20.7@4435,1320 ; P18.2@4785,1330 4785,1385 4808,1408 5137,1408 5185,1360 P18.6@5185,1330 P18.7@5285,1330 5382.03,1232.97 5622.97,1232.97 5650,1260 5650,1272 ; C4.2@4800,3140 4980,2960 C9.2@5755,2960 6165,2960 6175,2970 C10.2@6575,2970 ; P19.2@5650,1330 5650,1272 ; P17.2@6025,1320 6025,1267 ; IC1.20@6225,4970 P2.1@6460,4970 ; ST9.1@6340,8675 ST9.2@6536,8675 7002.97,8675 7005,8677.03 7317.97,8677.03 7365,8630 P25.1@7365,8560 P24.4@7735,8560 7735,8507 7760,8482 8407,8482 P21.4@8475,8550 8520,8472 9434,8472 9495,8533 ; ST6.2@6539,1185 6025,1240 6025,1267 ; R4.2@6905,1735 6992.58,1822.58 7556.51,1822.58 D1.1@7669.09,1710 ; C1.2@7405,3475 8800,3475 8864.8,3410.2 IC2.5@8864.8,3151.77 ; ST5.2@7849,1200 ST5.1@8045,1200 8210,1365 C17.2@10000,1365 10076,1289 10789,1289 C15.2@10845,1345 10921,1269 11564,1269 C13.2@11660,1365 11751.12,1273.88 12148.88,1273.88 12220,1345 P32.2@12480,1345 ; U8.3@9495,8595 9495,8533 ; CS1.3@9505,4680 10002.5,5177.5 10522.5,5177.5 IC8.20@10765,4935 P31.1@10955,4935 11560,4935 11610,4885 U7.3@11610,4805 ; IC4.9@10360,5920 10442,5838 11048,5838 IC5.1@11120,5910 11500,6290 C7.2@11500,6590 11600,6490 11983,6490 12114,6621 12375,6621 12436,6560 P3.2@12495,6560 ; U3.13@10725,7895 U3.4@10425,7895 10037,7895 10005,7863 9722,7863 9495,8090 9495,8533 ; U3.15@10725,8095 10869,8095 10912,8138 11560,8138 11605,8093 U9.3@11605,8030 ; D5.1@11434.09,4290 11525.09,4199 12079,4199 12230,4350 P29.7@12465,4350 ; 5650,1272 5680,1242 6000,1242 6025,1267
GREEN: ARD1.34 P12.15 U3.10 | length 2621
  Top Layer w10: P12.15@10020,6585 10084.53,6649.53 10084.53,7751.47 v1(10065,7771)
  Bottom Layer w10: ARD1.34@9390,6585 9419.53,6585 9464.53,6630 9975,6630 P12.15@10020,6585 ; v1(10065,7771) 10328,7771 10359,7740 10580,7740 U3.10@10725,7595
GREEN_OP: P6.3 U3.11 | length 1924.6
  Bottom Layer w25: U3.11@10725,7695 12190,7695 P6.3@12515,8020
HARDSTOP_MSP_LED: IC1.2 P1.2 R16.1 | length 5894.8
  Top Layer w10: R16.1@2830,8150 2995,7985 2995,5354 v1(3479,4870)
  Bottom Layer w10: v1(3479,4870) P1.2@5595,4870 IC1.2@5825,4870
HS_3: IC1.3 P1.3 | length 230
  Bottom Layer w10: P1.3@5595,4770 IC1.3@5825,4770
HS_4: IC1.4 P1.4 | length 230
  Bottom Layer w10: P1.4@5595,4670 IC1.4@5825,4670
HS_5: IC1.5 P1.5 | length 230
  Bottom Layer w10: P1.5@5595,4570 IC1.5@5825,4570
HS_8: IC1.8 P1.8 | length 230
  Bottom Layer w10: P1.8@5595,4270 IC1.8@5825,4270
HS_9: IC1.9 P1.9 | length 230
  Bottom Layer w10: P1.9@5595,4170 IC1.9@5825,4170
HS_10: IC1.10 P1.10 | length 230
  Bottom Layer w10: P1.10@5595,4070 IC1.10@5825,4070
HS_12: IC1.12 P2.9 | length 235
  Bottom Layer w10: IC1.12@6225,4170 P2.9@6460,4170
HS_13: IC1.13 P2.8 | length 235
  Bottom Layer w10: IC1.13@6225,4270 P2.8@6460,4270
HS_16: IC1.16 P2.5 | length 235
  Bottom Layer w10: IC1.16@6225,4570 P2.5@6460,4570
HS_17: IC1.17 P2.4 | length 235
  Bottom Layer w10: IC1.17@6225,4670 P2.4@6460,4670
